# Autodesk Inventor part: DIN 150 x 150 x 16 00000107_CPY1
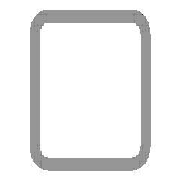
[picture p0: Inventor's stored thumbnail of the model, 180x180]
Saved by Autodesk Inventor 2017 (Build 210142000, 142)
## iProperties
Created: 2017-11
Part Number: DIN 150 x 150 x 16 00000107_CPY1
Material: Steel, Mild
Description: Cold formed welded structural hollow sections of non-alloy and fine grain structural steel
Document SubType Name: Modeling
Standard: DIN
Designer: iusti
Standard Revision: 2006-07
Standards Organization: DIN
Language: en-US
Size Designation: 150 x 150 x 16
Categories: <MemberInstance><Categories><Category DisplayName="Structural Shapes" InternalName="089c4875-fa83-4c05-b084-43b9cc11f5ed" Mnemonic="GRDR"><CategoryParameter Dis
Stock Number: 150 x 150 x 16
Mass: 90369.3 g
Surface Area: 14539.6 cm^2
Volume: 11512 cm^3
Density: 7.85 g/cm^3
Appearance: Semi-Polished
IsCustomPart: 1
G_W: 150.000 mm
G_H: 150.000 mm
G_L: 1539.608 mm
+5BB57DF3-1F1E-4AEC-9498-ACD0E832ECA7+CUTDETAIL2: Cut
_CCFamilyMember: 76
_CCFamilyDisplayName: DIN EN 10219-2 (Square Hollow Section - Cold Formed) - Cold formed welded structural hollow sections of non-alloy and fine grain structural steel
_FrameMemberDoc: Frame Member File
_Version: 15.0.0
_GetPNFromCC: 1
Author: iusti
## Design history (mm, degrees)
node "Start plane"
node "End plane"
sketch "Sketch"
  geometry: L1 (-75, -27)-(-75, 27); L2 (-27, 75)-(27, 75); L3 (75, 27)-(75, -27); L4 (27, -75)-(-27, -75); L5 (-27, 59)-(27, 59); L6 (59, 27)-(59, -27); L7 (27, -59)-(-27, -59); L8 (-59, -27)-(-59, 27); L9 (0, 118.918)-(0, -118.918) reference; L10 (-118.918, 0)-(118.918, 0) reference; A1 r 48 centre (-27, -27) between (-75, -27) and (-27, -75); A2 r 48 centre (-27, 27) between (-27, 75) and (-75, 27); A3 r 48 centre (27, 27) between (75, 27) and (27, 75); A4 r 48 centre (27, -27) between (27, -75) and (75, -27); A5 r 32 centre (-27, 27) between (-27, 59) and (-59, 27); A6 r 32 centre (27, 27) between (59, 27) and (27, 59); A7 r 32 centre (27, -27) between (27, -59) and (59, -27); A8 r 32 centre (-27, -27) between (-59, -27) and (-27, -59)
  constraints: 16 end point, 16 point on circle, 8 centre point, 8 tangent, 4 parallel, 3 equal radius, 2 perpendicular, 7 other
  dimensions: "d7" = 48 radius of A1 (= G_IR); "d10" = 150 distance between parallel lines of L2 L4 (= G_H); "d11" = 150 distance between parallel lines of L1 L3 (= G_W); "d12" = 16 distance between parallel lines of L3 L6 (= G_T); "d15" = 75 distance between parallel lines of L2 L10 (= 0.5 x d10); "d16" = 75 distance between parallel lines of L9 L3 (= 0.5 x d11)
extrude "Body" new body sketch "Sketch" stored distance "d3" = 1539.60835 (= G_L); taper "d4" = 0 deg
node "Driven Length"
  sketch "Sketch3"
    geometry: L1 (0, 0)-(10, 0) reference
    constraints: 2 end point, 1 horizontal
  workplane "Work Plane3"
  sketch "Sketch4"
    geometry: L1 (-2, 0)-(12, 0) reference; L2 (-2, 1539.608)-(12, 1539.608) reference
    dimensions: "d18" = 1539.60835 distance between parallel lines of L1 L2 (derived)
workplane "Work Plane5"
split "Split2"
body "Solid1"
other parameters: "G_W" = 150 [user parameter; used in 1 equation term], "G_H" = 150 [user parameter; used in 1 equation term], "G_T" = 16 [user parameter; used in 1 equation term], "G_IR" = 48 [user parameter; used in 1 equation term], "G_L" = 1539.60835 (= d18) [user parameter; used in 1 equation term], "G_OFFSET_START" = 0 [user parameter; used in 1 equation term], "G_OFFSET_END" = -75 [user parameter; used in 1 equation term], "d13" = 0 (computed from G_OFFSET_START), "d14" = 1539.60835 (= G_OFFSET_END + B_L), "B_L" = 1614.60835 [user parameter; used in 1 equation term], "d17" = 90 deg
